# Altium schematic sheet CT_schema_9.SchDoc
size 277 x 170 mm
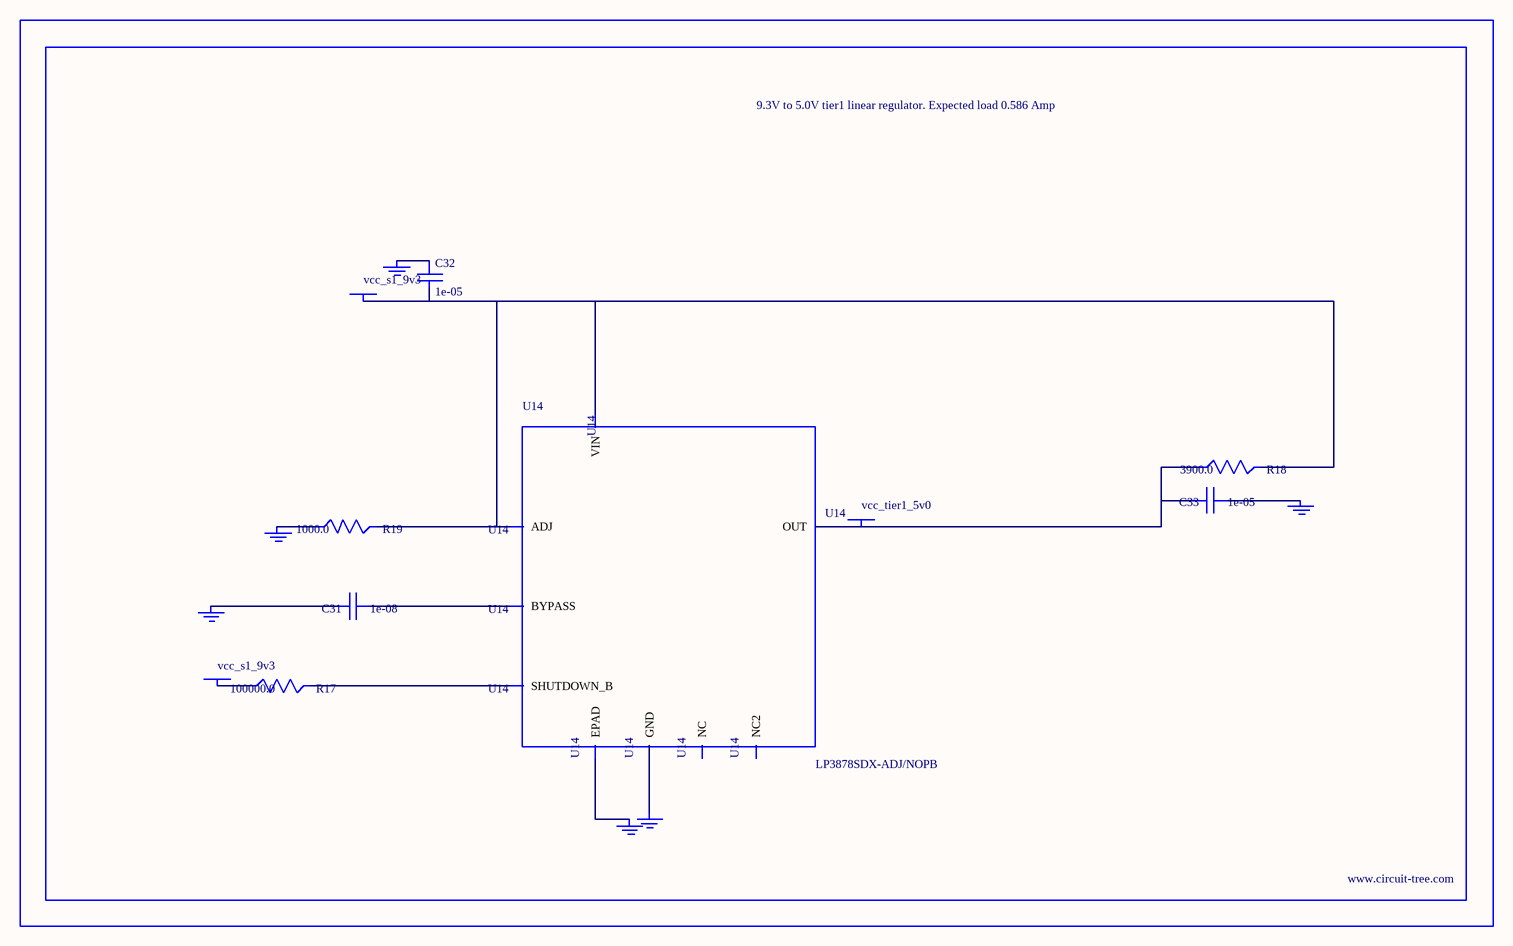
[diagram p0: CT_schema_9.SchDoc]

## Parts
BORDER8  (no value)
C31  1e-08  [C0402]
C32  1e-05  [C1206]
C33  1e-05  [C1210]
GND_INSTANCE_8_0  (no value)
GND_INSTANCE_8_1  (no value)
GND_INSTANCE_8_2  (no value)
GND_INSTANCE_8_3  (no value)
GND_INSTANCE_8_4  (no value)
GND_INSTANCE_8_5  (no value)
POWER_INSTANCE_8_0  vcc_s1_9v3
POWER_INSTANCE_8_1  vcc_s1_9v3
POWER_INSTANCE_8_2  vcc_tier1_5v0
R17  100000.0  [R0603]
R18  3900.0  [R0603]
R19  1000.0  [R0603]
U14  LP3878SDX-ADJ/NOPB  [WSON-8]

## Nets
NetC31_1: C31.1 U14.1(BYPASS)
NetC31_2: C31.2 GND_INSTANCE_8_0.0(GND)
NetC32_1: C32.1 GND_INSTANCE_8_1.0(GND)
NetC32_2: C32.2 POWER_INSTANCE_8_0.0(PWR) R18.2 R19.2 U14.4(VIN) U14.6(ADJ)
NetC33_1: C33.1 GND_INSTANCE_8_2.0(GND)
NetC33_2: C33.2 POWER_INSTANCE_8_2.0(PWR) R18.1 U14.5(OUT)
NetGND_INSTANCE_8_3_0: GND_INSTANCE_8_3.0(GND) R19.1
NetGND_INSTANCE_8_4_0: GND_INSTANCE_8_4.0(GND) U14.PAD(EPAD)
NetGND_INSTANCE_8_5_0: GND_INSTANCE_8_5.0(GND) U14.3(GND)
NetPOWER_INSTANCE_8_1_0: POWER_INSTANCE_8_1.0(PWR) R17.1
NetR17_2: R17.2 U14.8(SHUTDOWN_B)

Not connected (* = marked no-connect by the designer): U14 2(NC) 7(NC2)

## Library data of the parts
BORDER8 = BORDER_PAGE8
C31 = C0402C103K3RAC
C32 = C1206C106K3RACTU
C33 = GRM32DR61E106MA12L
GND_INSTANCE_8_0-GND_INSTANCE_8_5 = GND
POWER_INSTANCE_8_0-POWER_INSTANCE_8_2 = PWR
R17 = RC0603JR-07100KL
R18 = RC0603JR-073K9L
R19 = RC0603JR-071KL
